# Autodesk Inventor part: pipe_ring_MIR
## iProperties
Shininess: 64.0
Length Units: 11272
Angle Units: 11279
Time Units: 11290
Mass Units: 11286
Length Display Precision: 3
Angle Display Precision: 2
Compacted: True
Part Number: pipe_ring_MIR
Document SubType Name: Modeling
Created: 2004-08
Designer: John Blackburn
Material: Default
Manufacturer: Standard
Standards Organization: Custom
Density: 0.0
Volumn: 0.0
Area: 0.0
PropertySet Name: Model Information
Control State: 0
Master: False
Checked Out: False
Author: John Blackburn
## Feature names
1. Derived Body1 [Tagging]
